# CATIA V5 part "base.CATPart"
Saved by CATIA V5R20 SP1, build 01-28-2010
Part number: base
Bounding box of the stored display mesh (mm): x -500 to 500, y -350 to 350, z 0 to 410
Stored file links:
  C:\Users\Orange\Desktop\Assembly Design-8\base.CATPart
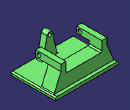
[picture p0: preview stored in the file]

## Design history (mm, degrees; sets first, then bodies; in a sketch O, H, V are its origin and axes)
Body1 (main body)
  Sketch1 on xy-plane, origin (0, 0, 0), H (1, 0, 0), V (0, 1, 0)
    line L1 (500, 350) -> (500, -350)
    line L2 (500, -350) -> (-500, -350)
    line L3 (-500, -350) -> (-500, 350)
    line L4 (-500, 350) -> (500, 350)
    length L4 = 1000
    length L1 = 700
    vertical: L1 V, L3 V
    horizontal: L2 H, L4 H
    equidistance: L1 L3 O, L2 L4 O
  Pad1: profile Sketch1, direction (0, 0, 1), length 50
  Fillet1: radius 20, on edge [face of Pad1 from Sketch1.L1 | end face of Pad1]; edge [face of Pad1 from Sketch1.L3 | end face of Pad1]
  Sketch2 on end face of Pad1, origin (0, 0, 50), H (1, 0, 0), V (0, 1, 0)
    line L1 (-475, 300) -> (475, 300)
    line L2 (475, 300) -> (475, 100)
    line L3 (475, 100) -> (-475, 100)
    line L4 (-475, 100) -> (-475, 300)
    reference projected line E1 (500, 350) -> (-500, 350) from edge [face of Pad1 from Sketch1.L4 | end face of Pad1]
    length L1 = 950
    distance L1 E1 = 50
    length L2 = 200
    horizontal: L1 H, L3 H
    vertical: L2 V, L4 V
    symmetry: L2 L4 V
  Pad2: profile Sketch2, direction (0, 0, 1), length 360
  Draft1: PullDir end face of Pad1, Angle 17, SupportToDraft face of Pad2 from Sketch2.L2, Neutral end face of Pad1
  Draft2: PullDir end face of Pad1, Angle 17, SupportToDraft face of Pad2 from Sketch2.L4, Neutral end face of Pad1
  Sketch3 on face of Pad2 from Sketch2.L3, origin (0, 100, 0), H (1, 0, 0), V (0, 0, 1)
    point P1 (364.937, 410)
    line L1 (364.937, 410) -> (284.937, 410)
    line L2 (284.937, 410) -> (284.937, 310)
    line L3 (284.937, 310) -> (364.937, 310)
    line L4 (364.937, 310) -> (364.937, 410)
    point P2 (284.937, 410)
    point P3 (284.937, 310)
    point P4 (364.937, 310)
    reference projected point E1 (364.937, 410) from vertex [end face of Pad2 | face of Pad2 from Sketch2.L2 | face of Pad2 from Sketch2.L3]
    point P5 (-364.937, 410)
    point P6 (-284.937, 410)
    point P7 (-284.937, 310)
    point P8 (-364.937, 310)
    line L5 (-364.937, 410) -> (-284.937, 410)
    line L6 (-284.937, 410) -> (-284.937, 310)
    line L7 (-284.937, 310) -> (-364.937, 310)
    line L8 (-364.937, 310) -> (-364.937, 410)
    length L2 = 100
    length L1 = 80
    horizontal: L1 H, L3 H
    vertical: L2 V, L4 V
    coincidence: P1 E1
    symmetry: P1 P5 V, P2 P6 V, P3 P7 V, P4 P8 V, L1 L5 V, L2 L6 V, L3 L7 V, L4 L8 V
  Pad3: profile Sketch3, direction (0, -1, 0), length 200
  Sketch4 on face of Pad2 from Sketch2.L3, origin (0, 100, 0), H (1, 0, 0), V (0, 0, 1)
    line L1 (284.937, 410) -> (-284.937, 410)
    line L2 (-284.937, 410) -> (-284.937, 250)
    line L3 (-284.937, 250) -> (284.937, 250)
    line L4 (284.937, 250) -> (284.937, 410)
    reference projected line E1 (284.937, 410) -> (284.937, 310) from edge [face of Pad3 from Sketch3.L2 | end face of Pad3]
    reference projected line E2 (-284.937, 310) -> (-284.937, 410) from edge [face of Pad3 from Sketch3.L6 | end face of Pad3]
    reference projected line E3 (-475, 410) -> (475, 410) from edge [face of Pad2 from Sketch2.L3 | face of Pad3]
    length L4 = 160
    horizontal: L1 H, L3 H
    vertical: L2 V, L4 V
    coincidence: L4 E1, L2 E2, L1 E3
  Pocket1: profile Sketch4, direction (0, 1, 0), through (limit type 3)
  Fillet2: radius 20, on edge [face of Pocket1 | face of Pocket1 from Sketch4.L3]; edge [face of Pocket1 from Sketch4.L3 | face of Pad3]
  Sketch5 on face of Pad2 from Sketch2.L3, origin (0, 100, 0), H (1, 0, 0), V (0, 0, 1)
    point P1 (364.937, 452.3643)
    line L1 (364.937, 452.3643) -> (364.937, 310)
    point P2 (364.937, 310)
    line L2 (364.937, 310) -> (475, 50)
    point P3 (475, 50)
    line L3 (475, 50) -> (364.937, 452.3643)
    reference projected line E1 (364.937, 310) -> (364.937, 410) from edge [face of Pad3 from Sketch3.L4 | end face of Pad3]
    reference projected point E2 (364.937, 310) from vertex [face of Pad3 from Sketch3.L4 | face of Pad3 from Sketch3.L3 | end face of Pad3]
    reference projected point E3 (475, 50) from vertex [face of Pad2 from Sketch2.L3 | face of Pad2 from Sketch2.L2 | end face of Pad1]
    point P4 (-364.937, 452.3643)
    point P5 (-364.937, 310)
    point P6 (-475, 50)
    line L4 (-364.937, 452.3643) -> (-364.937, 310)
    line L5 (-364.937, 310) -> (-475, 50)
    line L6 (-475, 50) -> (-364.937, 452.3643)
    vertical: L1 V
    coincidence: L1 E1, P2 E2, E3 P3
    symmetry: P1 P4 V, P2 P5 V, P3 P6 V, L1 L4 V, L2 L5 V, L3 L6 V
  Pocket2: profile Sketch5, direction (0, 1, 0), through (limit type 3)
  Fillet3: radius 20, on edge [end face of Pad1 | face of Pocket2 from Sketch5.L2]; edge [face of Pocket2 from Sketch5.L5 | end face of Pad1]
  Sketch6 on face of Pad3, origin (364.937, 0, 0), H (0, 1, 0), V (0, 0, 1)
    circle A1 centre (-50, 360) radius 30
    point P1 (-50, 360)
    reference projected line E1 (100, 310) -> (-100, 310) from edge [face of Pad3 | face of Pad3 from Sketch3.L3]
    reference projected line E2 (-100, 310) -> (-100, 410) from edge [face of Pad3 | end face of Pad3]
    radius A1 = 30
    distance P1 E1 = 50
    distance P1 E2 = 50
  Pocket3: profile Sketch6, direction (-1, 0, 0), through (limit type 3)
  Sketch7 on face of Pad1 from Sketch1.L2, origin (0, -350, 0), H (1, 0, 0), V (0, 0, 1)
    point P1 (-188.9292, 50)
    line L1 (111.3437, 65.6712) -> (43.9333, 369.7398)
    line L2 (-43.9333, 369.7398) -> (-111.3437, 65.6712)
    point P3 (-43.9333, 369.7398)
    arc A1 centre (0, 360) radius 45 from (43.9333, 369.7398) to (-43.9333, 369.7398) ccw
    point P5 (-43.9333, 369.7398)
    arc A2 centre (-130.8696, 70) radius 20 from (-111.3437, 65.6712) to (-130.8696, 50) cw
    point P6 (-111.3437, 65.6712)
    point P7 (-130.8696, 50)
    point P9 (130.8696, 50)
    point P10 (111.3437, 65.6712)
    arc A3 centre (130.8696, 70) radius 20 from (111.3437, 65.6712) to (130.8696, 50) ccw
    line L3 (-130.8696, 50) -> (130.8696, 50)
    circle A4 centre (0, 360) radius 25
    reference projected line E1 (-500, 50) -> (500, 50) from edge [face of Pad1 from Sketch1.L2 | end face of Pad1]
    radius A2 = 20
    distance A1 L3 = 355
    radius A4 = 25
    radius A1 = 45
    angle L1 L2 = 25
    tangency: A1 L1, L2 A1, A2 L2, L3 A2
    coincidence: P5 L2, P5 P3, L3 E1
    symmetry: P7 P9 V, P6 P10 V, A2 A3 V, L1 L2 V
  Pad4: profile Sketch7, direction (0, -1, 0), length -110, opposite side length 20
